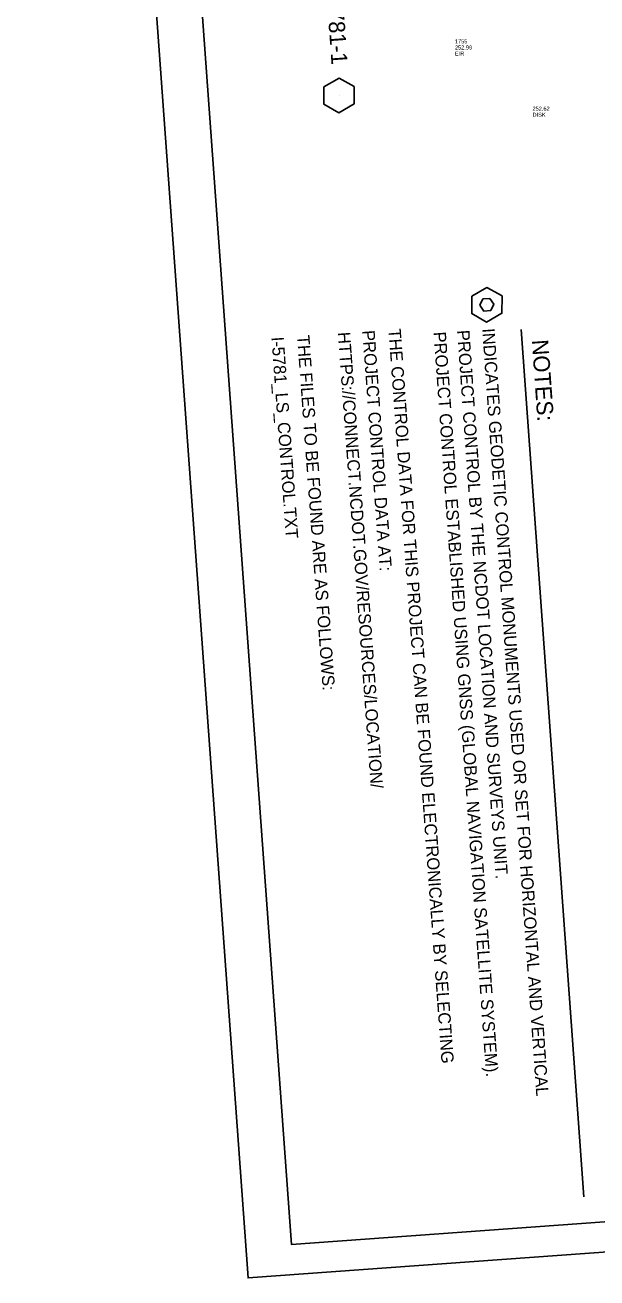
# Model space of a CAD drawing. Extents: x 2130621 to 2131998, y 642516 to 644503.
# Drawn here: x 2130621 to 2130973, y 642516 to 643289 of the extents above; entities that cross this region are included whole.
import ezdxf

# ---------------------------------------------------------------- set-up
doc = ezdxf.new("R2010")
doc.units = 0
for name, color, linetype in [('CTL North Arrow NAD 83 NA 2011 CELL', 7, 'Continuous'), ('CTL Primary Horizontal and Vertical CELL', 7, 'Continuous'), ('CTL Primary Horizontal and Vertical Text', 7, 'Continuous'), ('CTL Sheet Border CELL', 7, 'Continuous'), ('CTL Sheet Notes CELL', 7, 'Continuous'), ('Default', 7, 'Continuous'), ('Exist Property Iron Pin Cogo Comment', 7, 'Continuous'), ('Exist Property Iron Pin Cogo Elevation', 7, 'Continuous'), ('Exist Property Iron Pin Cogo Number', 7, 'Continuous'), ('Exist Right of Way Monument Cogo Comment', 7, 'Continuous'), ('Exist Right of Way Monument Cogo Elevation', 7, 'Continuous'), ('Sheet Plot Border Outside CELL', 7, 'Continuous')]:
    doc.layers.add(name, color=color, linetype=linetype)

# ---------------------------------------------------------------- blocks, each defined once
blk = doc.blocks.new('CTL GPS HORIZONTAL')
at = {"layer": 'CTL Sheet Notes CELL'}
blk.add_lwpolyline([(0, -0.07375), (-0.06425, -0.03725), (-0.06425, 0.0365), (0, 0.07375), (0.06425, 0.03725), (0.06425, -0.03725), (0, -0.07375)], dxfattribs=at)
at = {"layer": 'Default'}
blk.add_line((0, 0), (0, 0), dxfattribs=at)

msp = doc.modelspace()

# ---------------------------------------------------------------- linework, layer by layer
at = {"layer": 'CTL Primary Horizontal and Vertical CELL'}
for p, q in [((2130814.25, 643245.35), (2130814.25, 643245.35)), ((2130905.38, 643116.17), (2130905.38, 643116.17))]:
    msp.add_line(p, q, dxfattribs=at)
for points in [[(2130804.95, 643250.74), (2130814.31, 643255.96), (2130823.67, 643250.82), (2130823.52, 643240.09), (2130814.16, 643234.65), (2130804.95, 643239.87)], [(2130896.07, 643121.56), (2130905.43, 643126.78), (2130914.79, 643121.63), (2130914.65, 643110.9), (2130905.29, 643105.47), (2130896.07, 643110.69)]]:
    msp.add_lwpolyline(points, close=True, dxfattribs=at)
at = {"layer": 'CTL Sheet Border CELL'}
msp.add_lwpolyline([(2131968.81, 642621.99), (2131846.3, 644313.22), (2130662.45, 644227.46), (2130784.96, 642536.24)], close=True, dxfattribs=at)
at = {"layer": 'CTL Sheet Notes CELL'}
msp.add_line((2130926.54, 643100.85), (2130965.31, 642565.64), dxfattribs=at)
at = {"layer": 'Sheet Plot Border Outside CELL'}
msp.add_lwpolyline([(2130620.63, 644413.7), (2130758.12, 642515.65), (2131992.67, 642605.07), (2131855.18, 644503.13)], close=True, dxfattribs=at)

# ---------------------------------------------------------------- block references
at = {"layer": 'CTL North Arrow NAD 83 NA 2011 CELL', "xscale": 58.50000000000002, "yscale": 58.50000000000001, "rotation": -85.85693606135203}
msp.add_blockref('CTL GPS HORIZONTAL', (2130905.38, 643116.17), dxfattribs=at)

# ---------------------------------------------------------------- texts
at = {"layer": 'CTL Primary Horizontal and Vertical Text'}
msp.add_text('I5781-1', height=10, rotation=274.08714, dxfattribs=at).set_placement((2130806.41, 643309.36))
at = {"layer": 'CTL Sheet Notes CELL'}
for s, height, rotation, p in [('I-5781_LS_CONTROL.TXT', 7.6305, 274.14306, (2130772.51, 643096.15)), ('THE FILES TO BE FOUND ARE AS FOLLOWS:', 7.6305, 274.14306, (2130788.32, 643097.29)), ('HTTPS://CONNECT.NCDOT.GOV/RESOURCES/LOCATION/', 7.6305, 274.14306, (2130813.47, 643099.11)), ('PROJECT CONTROL DATA AT:', 7.6305, 274.14306, (2130828.56, 643100.2)), ('THE CONTROL DATA FOR THIS PROJECT CAN BE FOUND ELECTRONICALLY BY SELECTING', 7.6305, 274.14306, (2130844.67, 643101.16)), ('PROJECT CONTROL ESTABLISHED USING GNSS (GLOBAL NAVIGATION SATELLITE SYSTEM).', 7.6305, 274.03782, (2130872.5, 643099.28)), ('PROJECT CONTROL BY THE NCDOT LOCATION AND SURVEYS UNIT.', 7.6305, 274.03782, (2130887.02, 643100.34)), ('INDICATES GEODETIC CONTROL MONUMENTS USED OR SET FOR HORIZONTAL AND VERTICAL ', 7.6305, 274.03782, (2130902.48, 643101.4)), ('NOTES:', 10.174, 274.03782, (2130933.09, 643094.38))]:
    msp.add_text(s, height=height, rotation=rotation, dxfattribs=at).set_placement(p)
at = {"layer": 'Exist Property Iron Pin Cogo Comment'}
msp.add_text('EIR', height=2.5, dxfattribs=at).set_placement((2130885.73, 643269.93))
msp.add_text('EIR', height=2.5, dxfattribs=at).set_placement((2130885.73, 643269.93))
at = {"layer": 'Exist Property Iron Pin Cogo Elevation'}
msp.add_text('252.99', height=2.5, dxfattribs=at).set_placement((2130885.73, 643273.68))
at = {"layer": 'Exist Property Iron Pin Cogo Number'}
msp.add_text('1755', height=2.5, dxfattribs=at).set_placement((2130885.73, 643277.43))
msp.add_text('1755', height=2.5, dxfattribs=at).set_placement((2130885.73, 643277.43))
at = {"layer": 'Exist Right of Way Monument Cogo Comment'}
msp.add_text('DISK', height=2.5, dxfattribs=at).set_placement((2130933.58, 643232.17))
msp.add_text('DISK', height=2.5, dxfattribs=at).set_placement((2130933.58, 643232.17))
at = {"layer": 'Exist Right of Way Monument Cogo Elevation'}
msp.add_text('252.62', height=2.5, dxfattribs=at).set_placement((2130933.58, 643235.92))

doc.saveas('drawing.dxf')
